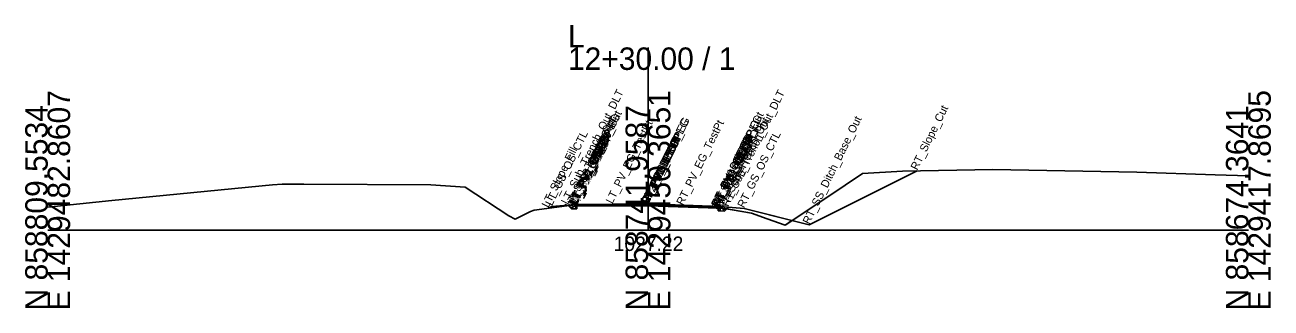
# Model space of a CAD drawing. Extents: x -26 to 2303, y -10 to 19558.
# Drawn here: x 1147.2 to 1302.8, y 490.3 to 525.6 of the extents above; entities that cross this region are included whole.
import ezdxf

# ---------------------------------------------------------------- set-up
doc = ezdxf.new("R2010")
doc.units = 0
for name, color, linetype in [('Default', 7, 'Continuous'), ('Exist CMT Pavement', 7, 'Continuous'), ('Exist Cross Section Cell', 7, 'Continuous'), ('Exist XS Center Line Elevation Label', 7, 'Continuous'), ('Exist XS Ground Line', 7, 'Continuous'), ('Old_Level_50', 7, 'Continuous'), ('Prop CMT Pvmt Course 1', 7, 'Continuous'), ('Prop CMT Pvmt Course 1 Wedge', 7, 'Continuous'), ('Prop CMT Pvmt Course 2', 7, 'Continuous'), ('Prop CMT Pvmt Course 2 Wedge', 7, 'Continuous'), ('Prop CMT Pvmt Surface', 7, 'Continuous'), ('Prop CMT Pvmt Surface Shoulder', 7, 'Continuous'), ('Prop CMT Pvmt Wedge Surface 1', 7, 'Continuous'), ('Prop CMT Pvmt Wedge Surface 2', 7, 'Continuous'), ('Prop CMT Shld Paved Course 1', 7, 'Continuous'), ('Prop CMT Shld Paved Course 2', 7, 'Continuous'), ('Prop CMT Slope Grass', 7, 'Continuous'), ('Prop CMT Subgrade Earthwork', 7, 'Continuous'), ('Prop XS Dump Level', 7, 'Continuous')]:
    doc.layers.add(name, color=color, linetype=linetype)

msp = doc.modelspace()

# ---------------------------------------------------------------- linework, layer by layer
at = {"layer": 'Exist CMT Pavement'}
for points in [[(1225, 503.22), (1216.09, 503.23)], [(1216.09, 503.23), (1220.55, 503.23)], [(1220.55, 503.23), (1225, 503.22)], [(1229.37, 503.04), (1225, 503.22)], [(1225, 503.22), (1233.75, 502.86)], [(1233.75, 502.86), (1229.37, 503.04)]]:
    msp.add_lwpolyline(points, dxfattribs=at)
at = {"layer": 'Exist Cross Section Cell'}
for p, q in [((1225, 500), (1225, 522.8)), ((1150, 500), (1225, 500)), ((1225, 500), (1300, 500))]:
    msp.add_line(p, q, dxfattribs=at)
at = {"layer": 'Exist XS Ground Line'}
msp.add_lwpolyline([(1150, 502.87), (1158.02, 503.73), (1178.1, 505.65), (1179.3, 505.77), (1181.99, 505.77), (1197.85, 505.65), (1202.14, 505.39), (1207.62, 501.8), (1208.4, 501.39), (1210.32, 502.34), (1210.77, 502.51), (1216.09, 503.23), (1216.4, 503.23), (1225.07, 503.22), (1225.49, 503.2), (1233.75, 502.86), (1234.05, 502.81), (1237.94, 502.15), (1239.87, 501.43), (1242.15, 500.66), (1247.45, 504.17), (1251.81, 507.09), (1256.79, 507.38), (1268.09, 507.6), (1286.07, 507.25), (1295.87, 506.93), (1300, 506.79)], dxfattribs=at)
at = {"layer": 'Old_Level_50'}
for p, q in [((1212.55, 502.75), (1215.03, 503.09)), ((1215.99, 503.22), (1214.98, 503.14)), ((1214.98, 503.14), (1215.03, 503.09)), ((1215.03, 503.09), (1214.98, 503.14)), ((1215.03, 503.09), (1215.99, 503.22)), ((1235.02, 502.87), (1234, 502.95)), ((1234, 502.95), (1234.16, 502.79)), ((1235.02, 502.87), (1234.83, 502.68)), ((1234.83, 502.68), (1235.02, 502.87)), ((1234.16, 502.79), (1234.83, 502.68)), ((1234.83, 502.68), (1237.94, 502.15))]:
    msp.add_line(p, q, dxfattribs=at)
for points in [[(1214.98, 503.14), (1213, 502.98), (1212.55, 502.75)], [(1242.98, 501.22), (1237, 502.71), (1235.02, 502.87)], [(1212.55, 502.75), (1212.55, 502.75)], [(1237.94, 502.15), (1239.87, 501.43), (1242.15, 500.66), (1242.98, 501.22)]]:
    msp.add_lwpolyline(points, dxfattribs=at)
at = {"layer": 'Prop CMT Pvmt Course 1'}
for points in [[(1225, 503.28), (1216, 503.22)], [(1216, 503.22), (1216, 503.01)], [(1216, 503.01), (1216.09, 503.01)], [(1216.09, 503.1), (1225, 503.15)], [(1216.09, 503.01), (1216.09, 503.1)], [(1225, 503.07), (1225, 503.28)], [(1225, 503.28), (1234, 502.95)], [(1225, 503.07), (1225, 503.28)], [(1225, 503.15), (1225, 503.07), (1225, 503.07)], [(1233.75, 502.84), (1225, 503.15)], [(1225, 503.15), (1225, 503.07), (1225, 503.07)], [(1234, 502.95), (1234, 502.74)], [(1233.75, 502.75), (1233.75, 502.84)], [(1234, 502.74), (1233.75, 502.75)]]:
    msp.add_lwpolyline(points, dxfattribs=at)
at = {"layer": 'Prop CMT Pvmt Course 1 Wedge'}
for points in [[(1225, 503.15), (1216.09, 503.1)], [(1225, 503.15), (1233.75, 502.84)]]:
    msp.add_lwpolyline(points, dxfattribs=at)
at = {"layer": 'Prop CMT Pvmt Course 2'}
for points in [[(1216.09, 503.01), (1216, 503.01)], [(1216, 503.01), (1216, 502.68)], [(1216.09, 502.68), (1216.09, 503.01)], [(1216, 502.68), (1216.09, 502.68)], [(1233.75, 502.42), (1233.75, 502.75)], [(1233.75, 502.75), (1234, 502.74)], [(1234, 502.41), (1233.75, 502.42)], [(1234, 502.74), (1234, 502.41)]]:
    msp.add_lwpolyline(points, dxfattribs=at)
at = {"layer": 'Prop CMT Pvmt Course 2 Wedge'}
for points in [[(1225, 503.07), (1216.09, 503.01)], [(1225, 503.07), (1233.75, 502.75)]]:
    msp.add_lwpolyline(points, dxfattribs=at)
at = {"layer": 'Prop CMT Pvmt Surface'}
for points in [[(1225, 503.28), (1216, 503.22)], [(1225, 503.28), (1234, 502.95)]]:
    msp.add_lwpolyline(points, dxfattribs=at)
at = {"layer": 'Prop CMT Pvmt Surface Shoulder'}
for points in [[(1216, 503.22), (1216, 503.22)], [(1234, 502.95), (1234, 502.95)]]:
    msp.add_lwpolyline(points, dxfattribs=at)
at = {"layer": 'Prop CMT Pvmt Wedge Surface 1'}
for points in [[(1216, 503.01), (1216, 503.22)], [(1216.09, 503.01), (1216, 503.01)], [(1225, 503.15), (1216.09, 503.1)], [(1216.09, 503.1), (1216.09, 503.01)], [(1225, 503.15), (1233.75, 502.84)], [(1234, 502.74), (1234, 502.95)], [(1233.75, 502.84), (1233.75, 502.75)], [(1233.75, 502.75), (1234, 502.74)]]:
    msp.add_lwpolyline(points, dxfattribs=at)
at = {"layer": 'Prop CMT Pvmt Wedge Surface 2'}
for points in [[(1216, 503.01), (1216, 503.22)], [(1225, 503.07), (1216, 503.01)], [(1225, 503.07), (1234, 502.74)], [(1234, 502.74), (1234, 502.95)]]:
    msp.add_lwpolyline(points, dxfattribs=at)
at = {"layer": 'Prop CMT Shld Paved Course 1'}
for points in [[(1216, 503.22), (1215.79, 503.01)], [(1215.79, 503.01), (1216, 503.01)], [(1216, 503.22), (1216, 503.22)], [(1216, 503.01), (1216, 503.22)], [(1234, 502.95), (1234, 502.95)], [(1234, 502.95), (1234.21, 502.74)], [(1234, 502.74), (1234, 502.95)], [(1234.21, 502.74), (1234, 502.74)]]:
    msp.add_lwpolyline(points, dxfattribs=at)
at = {"layer": 'Prop CMT Shld Paved Course 2'}
for points in [[(1215.79, 503.01), (1215.45, 502.67)], [(1216, 503.01), (1215.79, 503.01)], [(1215.79, 503.01), (1215.79, 503.01)], [(1216, 502.68), (1216, 503.01)], [(1215.45, 502.67), (1216, 502.68)], [(1234, 502.74), (1234.21, 502.74)], [(1234, 502.41), (1234, 502.74)], [(1234.55, 502.4), (1234, 502.41)], [(1234.21, 502.74), (1234.21, 502.74)], [(1234.21, 502.74), (1234.55, 502.4)]]:
    msp.add_lwpolyline(points, dxfattribs=at)
at = {"layer": 'Prop CMT Slope Grass'}
for points in [[(1234, 502.95), (1237, 502.71), (1245.15, 500.67), (1258.64, 507.42)], [(1216, 503.22), (1213, 502.98), (1212.55, 502.75)]]:
    msp.add_lwpolyline(points, dxfattribs=at)
at = {"layer": 'Prop CMT Subgrade Earthwork'}
for points in [[(1215.45, 502.67), (1214.98, 503.14)], [(1216.09, 502.68), (1216.11, 503.23)], [(1233.75, 502.42), (1233.73, 502.86)], [(1234.55, 502.4), (1235.02, 502.87)], [(1216, 502.68), (1215.45, 502.67)], [(1216.09, 502.68), (1216, 502.68)], [(1233.75, 502.42), (1234, 502.41)], [(1234, 502.41), (1234.55, 502.4)]]:
    msp.add_lwpolyline(points, dxfattribs=at)

# ---------------------------------------------------------------- texts
at = {"layer": 'Default'}
msp.add_text('-', height=0.0001, dxfattribs=at).set_placement((1150, 500))
at = {"layer": 'Exist Cross Section Cell'}
for s, p in [('L', (1215, 522.8)), ('12+30.00 / 1', (1215, 520))]:
    msp.add_text(s, height=2.8, dxfattribs=at).set_placement(p)
for s, p in [('E 1429482.8607', (1152.8, 490)), ('E 1429450.3651', (1227.8, 490)), ('E 1429417.8695', (1302.8, 490)), ('N 858809.5534', (1150, 490)), ('N 858741.9587', (1225, 490)), ('N 858674.3641', (1300, 490))]:
    msp.add_text(s, height=2.8, rotation=90, dxfattribs=at).set_placement(p)
at = {"layer": 'Exist XS Center Line Elevation Label'}
msp.add_text('1027.22', height=1.8, dxfattribs=at).set_placement((1220.71, 497.42))
at = {"layer": 'Prop XS Dump Level'}
for s, p in [('LT_Sub_Trench_Out_DLT', (1214.98, 503.14)), ('RT_Sub_Trench_Out_DLT', (1235.02, 502.87)), ('RT_Slope_Cut', (1258.64, 507.42)), ('LT_Sub_Trench_Out', (1215.45, 502.67)), ('LT_PV_OEEOP_EG', (1216.09, 503.23)), ('LT_PV_Sub_Tie_Out', (1216.11, 503.23)), ('RT_PV_IEEOP_EG', (1225, 503.22)), ('LT_PV_IEEOP_EG', (1225, 503.22)), ('RT_PV_Sub_Tie_Out', (1233.73, 502.86)), ('RT_PV_OEEOP_EG', (1233.75, 502.86)), ('RT_Sub_Trench_Out', (1234.55, 502.4)), ('RT_SS_Ditch_Base_Out', (1245.15, 500.67)), ('LT_PS2_Shelf_Out', (1215.79, 503.01)), ('LT_PV1_OEEOP', (1216.09, 503.1)), ('LT_PV2_OEEOP', (1216.09, 503.01)), ('LT_PV_EG_TestPt', (1220.55, 503.23)), ('RT_PV1_IEEOP', (1225, 503.15)), ('RT_PV2_IEEOP', (1225, 503.07)), ('RT_PV_EG_TestPt', (1229.37, 503.04)), ('RT_PV1_OEEOP', (1233.75, 502.84)), ('RT_PV2_OEEOP', (1233.75, 502.75)), ('RT_PS2_Shelf_Out', (1234.21, 502.74)), ('LT_GS_OS_CTL', (1213, 502.98)), ('LT_PS2_OEOP', (1215.79, 503.01)), ('LT_PV1_OEOT', (1216, 503.22)), ('LT_PS1_OEOP', (1216, 503.22)), ('LT_PV2_OEOT', (1216, 503.01)), ('LT_Sub_OEOT', (1216, 502.68)), ('LT_Sub_OEEOP', (1216.09, 502.68)), ('LT_PV1_IEEOP', (1225, 503.15)), ('LT_PV2_IEEOP', (1225, 503.07)), ('RT_Sub_OEEOP', (1233.75, 502.42)), ('RT_PV1_OEOT', (1234, 502.95)), ('RT_PS1_OEOP', (1234, 502.95)), ('RT_PV2_OEOT', (1234, 502.74)), ('RT_Sub_OEOT', (1234, 502.41)), ('RT_PS2_OEOP', (1234.21, 502.74)), ('RT_GS_OS_CTL', (1237, 502.71)), ('LT_Slope_Fill', (1212.55, 502.75)), ('PV1_PGL', (1225, 503.28)), ('PV2_PGL', (1225, 503.07))]:
    msp.add_text(s, height=1, rotation=63.5833, dxfattribs=at).set_placement(p)

doc.saveas('drawing.dxf')
